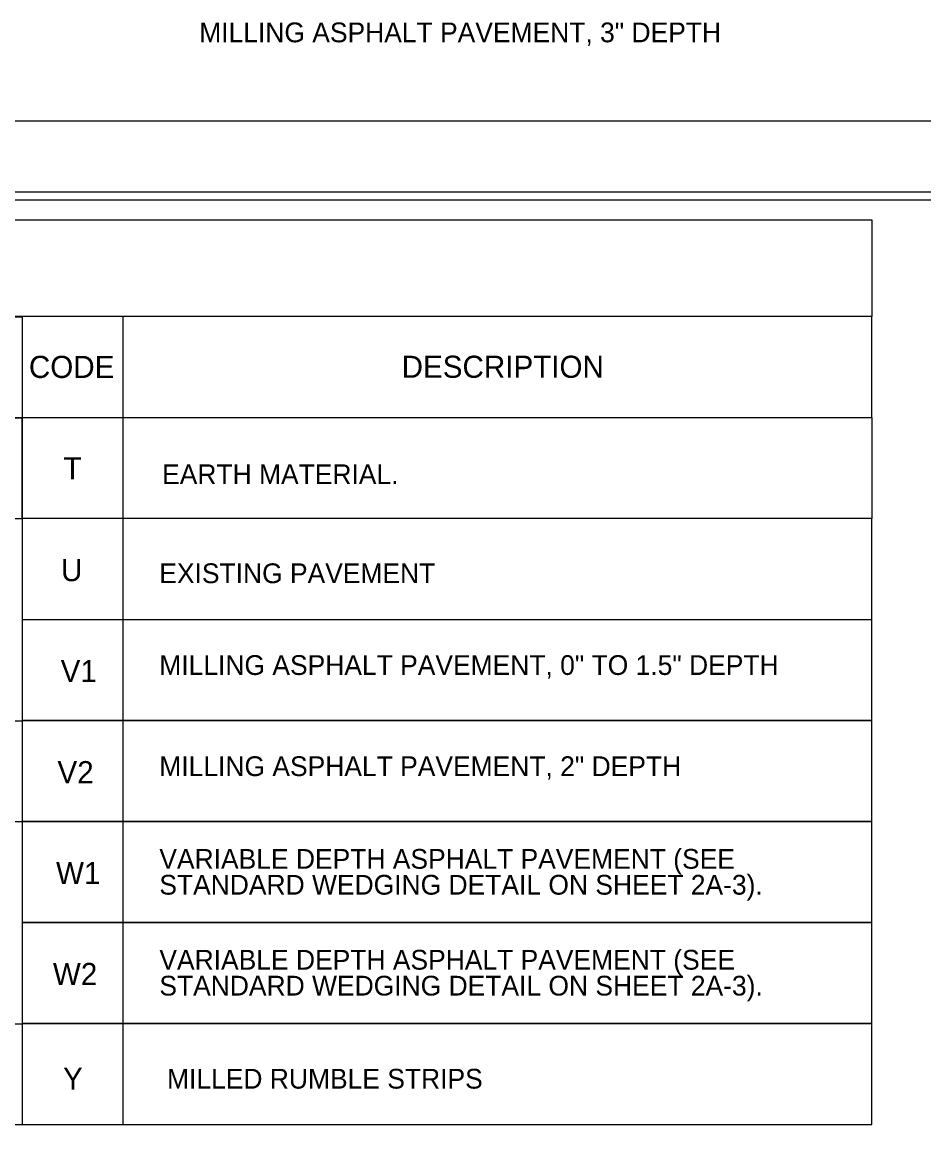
# Model space of a CAD drawing. Extents: x 2176024 to 2177225, y 75947 to 76635.
# Drawn here: x 2176794.1 to 2176839.7, y 76579.2 to 76635.5 of the extents above; entities that cross this region are included whole.
import ezdxf

# ---------------------------------------------------------------- set-up
doc = ezdxf.new("R2010")
doc.units = 0
for name, color, linetype in [('Old_Level_19', 7, 'Continuous'), ('Old_Level_21', 7, 'Continuous'), ('Prop Pavement Schedule Description CELL', 7, 'Continuous'), ('Sheet Cutting Line CELL', 7, 'Continuous'), ('Sheet Plot Border Inside CELL', 7, 'Continuous'), ('Sheet Plot Border Outside CELL', 7, 'Continuous'), ('Sheet Typical CELL', 7, 'Continuous')]:
    doc.layers.add(name, color=color, linetype=linetype)

msp = doc.modelspace()

# ---------------------------------------------------------------- linework, layer by layer
at = {"layer": 'Old_Level_19'}
msp.add_lwpolyline([(2176657.031, 76625.489), (2176837.114, 76625.489), (2176837.114, 76620.582), (2176657.031, 76620.582)], close=True, dxfattribs=at)
at = {"layer": 'Prop Pavement Schedule Description CELL'}
for p, q in [((2176799.23, 76615.473), (2176799.23, 76620.582)), ((2176799.23, 76605.248), (2176799.23, 76610.357)), ((2176799.23, 76600.133), (2176799.23, 76605.243)), ((2176799.23, 76595.023), (2176799.23, 76600.132)), ((2176799.23, 76589.912), (2176799.23, 76595.022)), ((2176799.232, 76584.8), (2176799.232, 76589.909)), ((2176799.232, 76579.692), (2176799.232, 76584.801))]:
    msp.add_line(p, q, dxfattribs=at)
for points in [[(2176730.687, 76615.466), (2176725.573, 76615.466), (2176725.573, 76620.58), (2176794.116, 76620.58), (2176794.116, 76615.466), (2176730.687, 76615.466), (2176730.687, 76620.58)], [(2176730.687, 76610.351), (2176725.573, 76610.351), (2176725.573, 76615.466), (2176794.116, 76615.466), (2176794.116, 76610.351), (2176730.687, 76610.351), (2176730.687, 76615.466)], [(2176799.23, 76610.357), (2176794.116, 76610.357), (2176794.116, 76615.472), (2176837.114, 76615.472), (2176837.114, 76610.357), (2176799.23, 76610.357), (2176799.23, 76615.472)], [(2176730.688, 76595.013), (2176725.574, 76595.013), (2176725.574, 76600.128), (2176794.117, 76600.128), (2176794.117, 76595.013), (2176730.688, 76595.013), (2176730.688, 76600.128)], [(2176730.689, 76579.671), (2176725.575, 76579.671), (2176725.575, 76584.785), (2176794.118, 76584.785), (2176794.118, 76579.671), (2176730.689, 76579.671), (2176730.689, 76584.785)]]:
    msp.add_lwpolyline(points, dxfattribs=at)
for points in [[(2176794.116, 76615.472), (2176837.114, 76615.472), (2176837.114, 76620.582), (2176794.116, 76620.582)], [(2176794.116, 76605.247), (2176837.114, 76605.247), (2176837.114, 76610.357), (2176794.116, 76610.357)], [(2176794.116, 76600.132), (2176837.114, 76600.132), (2176837.114, 76605.243), (2176794.116, 76605.243)], [(2176794.116, 76595.022), (2176837.114, 76595.022), (2176837.114, 76600.132), (2176794.116, 76600.132)], [(2176794.116, 76589.911), (2176837.114, 76589.911), (2176837.114, 76595.022), (2176794.116, 76595.022)], [(2176794.118, 76584.801), (2176837.116, 76584.801), (2176837.116, 76589.911), (2176794.118, 76589.911)], [(2176794.118, 76579.691), (2176837.116, 76579.691), (2176837.116, 76584.801), (2176794.118, 76584.801)]]:
    msp.add_lwpolyline(points, close=True, dxfattribs=at)
at = {"layer": 'Sheet Cutting Line CELL'}
msp.add_line((2176898.707, 76630.475), (2176629.267, 76630.475), dxfattribs=at)
at = {"layer": 'Sheet Plot Border Inside CELL'}
msp.add_lwpolyline([(2176897.987, 76626.883), (2176631.347, 76626.883), (2176631.347, 76458.067), (2176897.987, 76458.067)], close=True, dxfattribs=at)
at = {"layer": 'Sheet Plot Border Outside CELL'}
msp.add_lwpolyline([(2176898.707, 76630.475), (2176629.267, 76630.475), (2176629.267, 76454.475), (2176898.707, 76454.475)], close=True, dxfattribs=at)
at = {"layer": 'Sheet Typical CELL'}
msp.add_lwpolyline([(2176895.987, 76626.475), (2176655.987, 76626.475), (2176655.987, 76458.475), (2176895.987, 76458.475)], close=True, dxfattribs=at)

# ---------------------------------------------------------------- texts
at = {"layer": 'Old_Level_21'}
for s, p in [('CODE', (2176794.453, 76617.478)), ('DESCRIPTION', (2176813.317, 76617.485))]:
    msp.add_text(s, height=1.12, rotation=0, dxfattribs=at).set_placement(p)
at = {"layer": 'Prop Pavement Schedule Description CELL'}
for s, height, p in [('MILLING ASPHALT PAVEMENT, 3" DEPTH', 1, (2176803.073, 76634.469)), ('T', 1.12, (2176796.202, 76612.339)), ('EARTH MATERIAL.', 1, (2176801.195, 76612.105)), ('U', 1.12, (2176796.08, 76607.194)), ('EXISTING PAVEMENT', 1, (2176801.053, 76607.092)), ('V1', 1.12, (2176796.06, 76602.083)), ('MILLING ASPHALT PAVEMENT, 0" TO 1.5" DEPTH', 1, (2176801.053, 76602.446)), ('V2', 1.12, (2176795.899, 76596.964)), ('MILLING ASPHALT PAVEMENT, 2" DEPTH', 1, (2176801.053, 76597.327)), ('VARIABLE DEPTH ASPHALT PAVEMENT (SEE ', 1, (2176801.054, 76592.637)), ('W1', 1.12, (2176795.826, 76591.859)), ('STANDARD WEDGING DETAIL ON SHEET 2A-3).', 1, (2176801.054, 76591.326)), ('VARIABLE DEPTH ASPHALT PAVEMENT (SEE ', 1, (2176801.056, 76587.529)), ('W2', 1.12, (2176795.668, 76586.751)), ('STANDARD WEDGING DETAIL ON SHEET 2A-3).', 1, (2176801.056, 76586.219)), ('Y', 1.12, (2176796.181, 76581.455)), ('MILLED RUMBLE STRIPS', 1, (2176801.444, 76581.508))]:
    msp.add_text(s, height=height, dxfattribs=at).set_placement(p)

doc.saveas('drawing.dxf')
